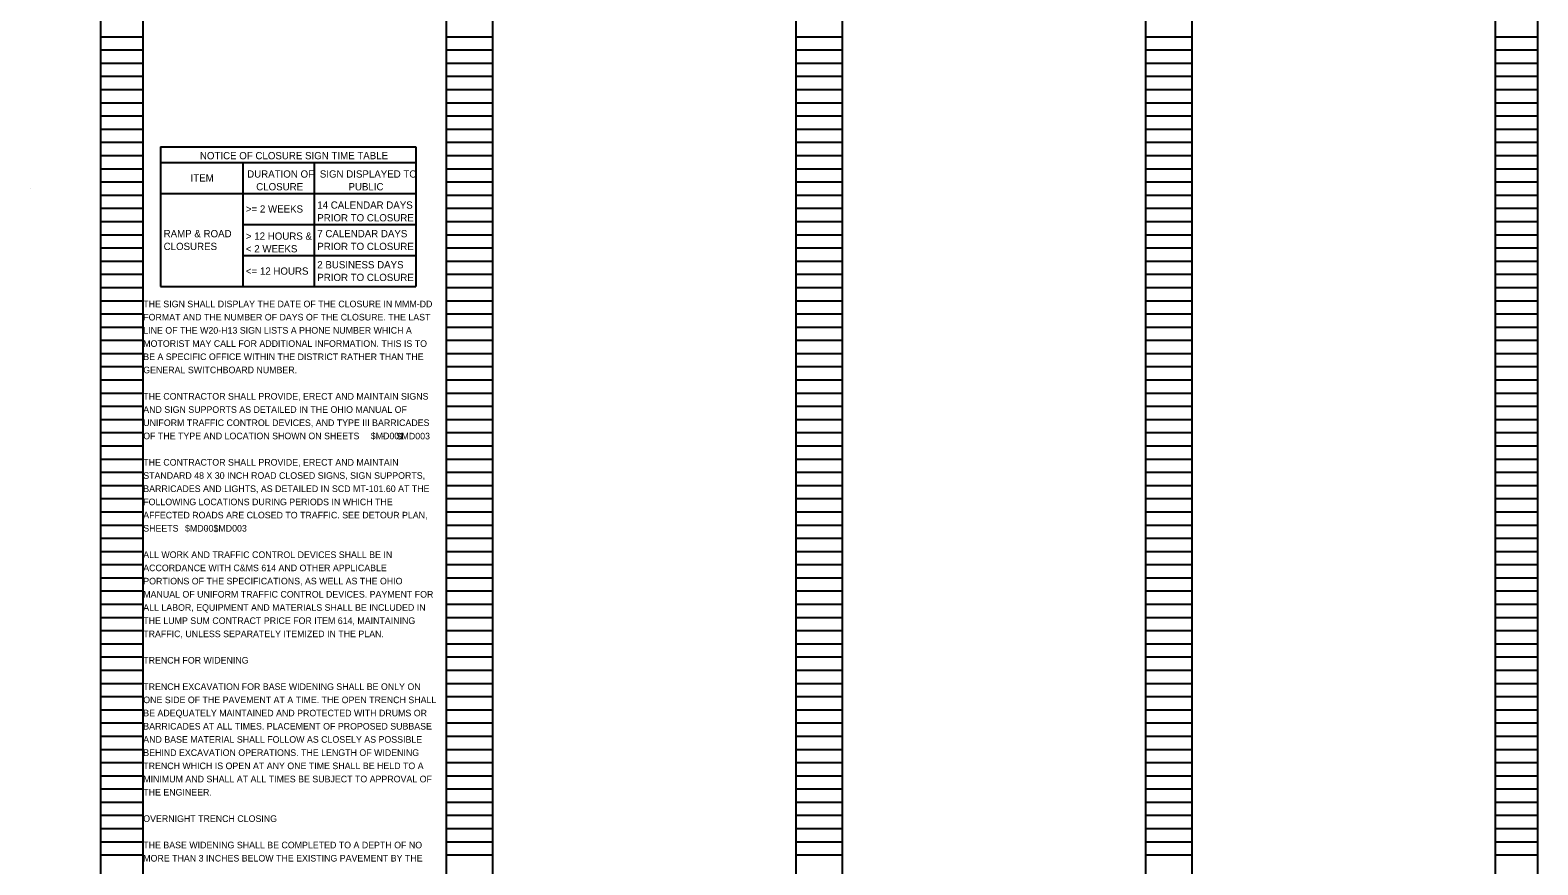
# Model space of a CAD drawing. Extents: x -9 to 32, y -122 to 20.
# Drawn here: x -0.28 to 31.72, y -15.02 to 2.69 of the extents above; entities that cross this region are included whole.
import ezdxf

# ---------------------------------------------------------------- set-up
doc = ezdxf.new("R2010")
doc.units = 0
doc.layers.add('SC_Scratch1', color=7, linetype='Continuous')
doc.layers.add('SH_Text', color=7, linetype='Continuous')

msp = doc.modelspace()

# ---------------------------------------------------------------- linework, layer by layer
at = {"layer": 'SC_Scratch1'}
for p, q in [((1.216, 0.306), (1.216, 20.466)), ((2.116, 0.306), (2.116, 20.466)), ((8.556, 0.306), (8.556, 20.466)), ((9.536, 0.306), (9.536, 20.466)), ((15.976, 0.306), (15.976, 20.466)), ((16.956, 0.306), (16.956, 20.466)), ((23.396, 0.306), (23.396, 20.466)), ((24.376, 0.306), (24.376, 20.466)), ((30.816, 0.306), (30.816, 20.466)), ((31.716, 0.306), (31.716, 20.466)), ((1.216, 2.546), (2.116, 2.546)), ((1.216, 2.266), (2.116, 2.266)), ((8.556, 2.546), (9.536, 2.546)), ((8.556, 2.266), (9.536, 2.266)), ((15.976, 2.546), (16.956, 2.546)), ((15.976, 2.266), (16.956, 2.266)), ((23.396, 2.546), (24.376, 2.546)), ((23.396, 2.266), (24.376, 2.266)), ((30.816, 2.546), (31.716, 2.546)), ((30.816, 2.266), (31.716, 2.266)), ((1.216, 1.986), (2.116, 1.986)), ((8.556, 1.986), (9.536, 1.986)), ((15.976, 1.986), (16.956, 1.986)), ((23.396, 1.986), (24.376, 1.986)), ((30.816, 1.986), (31.716, 1.986)), ((1.216, 1.706), (2.116, 1.706)), ((8.556, 1.706), (9.536, 1.706)), ((15.976, 1.706), (16.956, 1.706)), ((23.396, 1.706), (24.376, 1.706)), ((30.816, 1.706), (31.716, 1.706)), ((1.216, 1.426), (2.116, 1.426)), ((8.556, 1.426), (9.536, 1.426)), ((15.976, 1.426), (16.956, 1.426)), ((23.396, 1.426), (24.376, 1.426)), ((30.816, 1.426), (31.716, 1.426)), ((1.216, 1.146), (2.116, 1.146)), ((8.556, 1.146), (9.536, 1.146)), ((15.976, 1.146), (16.956, 1.146)), ((23.396, 1.146), (24.376, 1.146)), ((30.816, 1.146), (31.716, 1.146)), ((1.216, 0.866), (2.116, 0.866)), ((8.556, 0.866), (9.536, 0.866)), ((15.976, 0.866), (16.956, 0.866)), ((23.396, 0.866), (24.376, 0.866)), ((30.816, 0.866), (31.716, 0.866)), ((1.216, 0.586), (2.116, 0.586)), ((8.556, 0.586), (9.536, 0.586)), ((15.976, 0.586), (16.956, 0.586)), ((23.396, 0.586), (24.376, 0.586)), ((30.816, 0.586), (31.716, 0.586)), ((1.216, 0.306), (2.116, 0.306)), ((1.216, -19.854), (1.216, 0.306)), ((1.216, 0.306), (2.116, 0.306)), ((1.216, 0.026), (2.116, 0.026)), ((2.116, -19.854), (2.116, 0.306)), ((8.556, 0.306), (9.536, 0.306)), ((8.556, -19.854), (8.556, 0.306)), ((8.556, 0.306), (9.536, 0.306)), ((8.556, 0.026), (9.536, 0.026)), ((9.536, -19.854), (9.536, 0.306)), ((15.976, 0.306), (16.956, 0.306)), ((15.976, -19.854), (15.976, 0.306)), ((15.976, 0.306), (16.956, 0.306)), ((15.976, 0.026), (16.956, 0.026)), ((16.956, -19.854), (16.956, 0.306)), ((23.396, 0.306), (24.376, 0.306)), ((23.396, -19.854), (23.396, 0.306)), ((23.396, 0.306), (24.376, 0.306)), ((23.396, 0.026), (24.376, 0.026)), ((24.376, -19.854), (24.376, 0.306)), ((30.816, 0.306), (31.716, 0.306)), ((30.816, -19.854), (30.816, 0.306)), ((30.816, 0.306), (31.716, 0.306)), ((30.816, 0.026), (31.716, 0.026)), ((31.716, -19.854), (31.716, 0.306)), ((1.216, -0.254), (2.116, -0.254)), ((8.556, -0.254), (9.536, -0.254)), ((15.976, -0.254), (16.956, -0.254)), ((23.396, -0.254), (24.376, -0.254)), ((30.816, -0.254), (31.716, -0.254)), ((1.216, -0.534), (2.116, -0.534)), ((8.556, -0.534), (9.536, -0.534)), ((15.976, -0.534), (16.956, -0.534)), ((23.396, -0.534), (24.376, -0.534)), ((30.816, -0.534), (31.716, -0.534)), ((-0.284, -0.674), (-0.284, -0.674)), ((1.216, -0.814), (2.116, -0.814)), ((8.556, -0.814), (9.536, -0.814)), ((15.976, -0.814), (16.956, -0.814)), ((23.396, -0.814), (24.376, -0.814)), ((30.816, -0.814), (31.716, -0.814)), ((1.216, -1.094), (2.116, -1.094)), ((8.556, -1.094), (9.536, -1.094)), ((15.976, -1.094), (16.956, -1.094)), ((23.396, -1.094), (24.376, -1.094)), ((30.816, -1.094), (31.716, -1.094)), ((1.216, -1.374), (2.116, -1.374)), ((8.556, -1.374), (9.536, -1.374)), ((15.976, -1.374), (16.956, -1.374)), ((23.396, -1.374), (24.376, -1.374)), ((30.816, -1.374), (31.716, -1.374)), ((1.216, -1.654), (2.116, -1.654)), ((8.556, -1.654), (9.536, -1.654)), ((15.976, -1.654), (16.956, -1.654)), ((23.396, -1.654), (24.376, -1.654)), ((30.816, -1.654), (31.716, -1.654)), ((1.216, -1.934), (2.116, -1.934)), ((1.216, -2.214), (2.116, -2.214)), ((8.556, -1.934), (9.536, -1.934)), ((8.556, -2.214), (9.536, -2.214)), ((15.976, -1.934), (16.956, -1.934)), ((15.976, -2.214), (16.956, -2.214)), ((23.396, -1.934), (24.376, -1.934)), ((23.396, -2.214), (24.376, -2.214)), ((30.816, -1.934), (31.716, -1.934)), ((30.816, -2.214), (31.716, -2.214)), ((1.216, -2.494), (2.116, -2.494)), ((8.556, -2.494), (9.536, -2.494)), ((15.976, -2.494), (16.956, -2.494)), ((23.396, -2.494), (24.376, -2.494)), ((30.816, -2.494), (31.716, -2.494)), ((1.216, -2.774), (2.116, -2.774)), ((8.556, -2.774), (9.536, -2.774)), ((15.976, -2.774), (16.956, -2.774)), ((23.396, -2.774), (24.376, -2.774)), ((30.816, -2.774), (31.716, -2.774)), ((1.216, -3.054), (2.116, -3.054)), ((8.556, -3.054), (9.536, -3.054)), ((15.976, -3.054), (16.956, -3.054)), ((23.396, -3.054), (24.376, -3.054)), ((30.816, -3.054), (31.716, -3.054)), ((1.216, -3.334), (2.116, -3.334)), ((8.556, -3.334), (9.536, -3.334)), ((15.976, -3.334), (16.956, -3.334)), ((23.396, -3.334), (24.376, -3.334)), ((30.816, -3.334), (31.716, -3.334)), ((1.216, -3.614), (2.116, -3.614)), ((8.556, -3.614), (9.536, -3.614)), ((15.976, -3.614), (16.956, -3.614)), ((23.396, -3.614), (24.376, -3.614)), ((30.816, -3.614), (31.716, -3.614)), ((1.216, -3.894), (2.116, -3.894)), ((8.556, -3.894), (9.536, -3.894)), ((15.976, -3.894), (16.956, -3.894)), ((23.396, -3.894), (24.376, -3.894)), ((30.816, -3.894), (31.716, -3.894)), ((1.216, -4.174), (2.116, -4.174)), ((1.216, -4.454), (2.116, -4.454)), ((8.556, -4.174), (9.536, -4.174)), ((8.556, -4.454), (9.536, -4.454)), ((15.976, -4.174), (16.956, -4.174)), ((15.976, -4.454), (16.956, -4.454)), ((23.396, -4.174), (24.376, -4.174)), ((23.396, -4.454), (24.376, -4.454)), ((30.816, -4.174), (31.716, -4.174)), ((30.816, -4.454), (31.716, -4.454)), ((1.216, -4.734), (2.116, -4.734)), ((8.556, -4.734), (9.536, -4.734)), ((15.976, -4.734), (16.956, -4.734)), ((23.396, -4.734), (24.376, -4.734)), ((30.816, -4.734), (31.716, -4.734)), ((1.216, -5.014), (2.116, -5.014)), ((8.556, -5.014), (9.536, -5.014)), ((15.976, -5.014), (16.956, -5.014)), ((23.396, -5.014), (24.376, -5.014)), ((30.816, -5.014), (31.716, -5.014)), ((1.216, -5.294), (2.116, -5.294)), ((8.556, -5.294), (9.536, -5.294)), ((15.976, -5.294), (16.956, -5.294)), ((23.396, -5.294), (24.376, -5.294)), ((30.816, -5.294), (31.716, -5.294)), ((1.216, -5.574), (2.116, -5.574)), ((8.556, -5.574), (9.536, -5.574)), ((15.976, -5.574), (16.956, -5.574)), ((23.396, -5.574), (24.376, -5.574)), ((30.816, -5.574), (31.716, -5.574)), ((1.216, -5.854), (2.116, -5.854)), ((8.556, -5.854), (9.536, -5.854)), ((15.976, -5.854), (16.956, -5.854)), ((23.396, -5.854), (24.376, -5.854)), ((30.816, -5.854), (31.716, -5.854)), ((1.216, -6.134), (2.116, -6.134)), ((8.556, -6.134), (9.536, -6.134)), ((15.976, -6.134), (16.956, -6.134)), ((23.396, -6.134), (24.376, -6.134)), ((30.816, -6.134), (31.716, -6.134)), ((1.216, -6.414), (2.116, -6.414)), ((1.216, -6.694), (2.116, -6.694)), ((8.556, -6.414), (9.536, -6.414)), ((8.556, -6.694), (9.536, -6.694)), ((15.976, -6.414), (16.956, -6.414)), ((15.976, -6.694), (16.956, -6.694)), ((23.396, -6.414), (24.376, -6.414)), ((23.396, -6.694), (24.376, -6.694)), ((30.816, -6.414), (31.716, -6.414)), ((30.816, -6.694), (31.716, -6.694)), ((1.216, -6.974), (2.116, -6.974)), ((8.556, -6.974), (9.536, -6.974)), ((15.976, -6.974), (16.956, -6.974)), ((23.396, -6.974), (24.376, -6.974)), ((30.816, -6.974), (31.716, -6.974)), ((1.216, -7.254), (2.116, -7.254)), ((8.556, -7.254), (9.536, -7.254)), ((15.976, -7.254), (16.956, -7.254)), ((23.396, -7.254), (24.376, -7.254)), ((30.816, -7.254), (31.716, -7.254)), ((1.216, -7.534), (2.116, -7.534)), ((8.556, -7.534), (9.536, -7.534)), ((15.976, -7.534), (16.956, -7.534)), ((23.396, -7.534), (24.376, -7.534)), ((30.816, -7.534), (31.716, -7.534)), ((1.216, -7.814), (2.116, -7.814)), ((8.556, -7.814), (9.536, -7.814)), ((15.976, -7.814), (16.956, -7.814)), ((23.396, -7.814), (24.376, -7.814)), ((30.816, -7.814), (31.716, -7.814)), ((1.216, -8.094), (2.116, -8.094)), ((8.556, -8.094), (9.536, -8.094)), ((15.976, -8.094), (16.956, -8.094)), ((23.396, -8.094), (24.376, -8.094)), ((30.816, -8.094), (31.716, -8.094)), ((1.216, -8.374), (2.116, -8.374)), ((8.556, -8.374), (9.536, -8.374)), ((15.976, -8.374), (16.956, -8.374)), ((23.396, -8.374), (24.376, -8.374)), ((30.816, -8.374), (31.716, -8.374)), ((1.216, -8.654), (2.116, -8.654)), ((1.216, -8.934), (2.116, -8.934)), ((8.556, -8.654), (9.536, -8.654)), ((8.556, -8.934), (9.536, -8.934)), ((15.976, -8.654), (16.956, -8.654)), ((15.976, -8.934), (16.956, -8.934)), ((23.396, -8.654), (24.376, -8.654)), ((23.396, -8.934), (24.376, -8.934)), ((30.816, -8.654), (31.716, -8.654)), ((30.816, -8.934), (31.716, -8.934)), ((1.216, -9.214), (2.116, -9.214)), ((8.556, -9.214), (9.536, -9.214)), ((15.976, -9.214), (16.956, -9.214)), ((23.396, -9.214), (24.376, -9.214)), ((30.816, -9.214), (31.716, -9.214)), ((1.216, -9.494), (2.116, -9.494)), ((8.556, -9.494), (9.536, -9.494)), ((15.976, -9.494), (16.956, -9.494)), ((23.396, -9.494), (24.376, -9.494)), ((30.816, -9.494), (31.716, -9.494)), ((1.216, -9.774), (2.116, -9.774)), ((8.556, -9.774), (9.536, -9.774)), ((15.976, -9.774), (16.956, -9.774)), ((23.396, -9.774), (24.376, -9.774)), ((30.816, -9.774), (31.716, -9.774)), ((1.216, -10.054), (2.116, -10.054)), ((8.556, -10.054), (9.536, -10.054)), ((15.976, -10.054), (16.956, -10.054)), ((23.396, -10.054), (24.376, -10.054)), ((30.816, -10.054), (31.716, -10.054)), ((1.216, -10.334), (2.116, -10.334)), ((8.556, -10.334), (9.536, -10.334)), ((15.976, -10.334), (16.956, -10.334)), ((23.396, -10.334), (24.376, -10.334)), ((30.816, -10.334), (31.716, -10.334)), ((1.216, -10.614), (2.116, -10.614)), ((8.556, -10.614), (9.536, -10.614)), ((15.976, -10.614), (16.956, -10.614)), ((23.396, -10.614), (24.376, -10.614)), ((30.816, -10.614), (31.716, -10.614)), ((1.216, -10.894), (2.116, -10.894)), ((1.216, -11.174), (2.116, -11.174)), ((8.556, -10.894), (9.536, -10.894)), ((8.556, -11.174), (9.536, -11.174)), ((15.976, -10.894), (16.956, -10.894)), ((15.976, -11.174), (16.956, -11.174)), ((23.396, -10.894), (24.376, -10.894)), ((23.396, -11.174), (24.376, -11.174)), ((30.816, -10.894), (31.716, -10.894)), ((30.816, -11.174), (31.716, -11.174)), ((1.216, -11.454), (2.116, -11.454)), ((8.556, -11.454), (9.536, -11.454)), ((15.976, -11.454), (16.956, -11.454)), ((23.396, -11.454), (24.376, -11.454)), ((30.816, -11.454), (31.716, -11.454)), ((1.216, -11.734), (2.116, -11.734)), ((8.556, -11.734), (9.536, -11.734)), ((15.976, -11.734), (16.956, -11.734)), ((23.396, -11.734), (24.376, -11.734)), ((30.816, -11.734), (31.716, -11.734)), ((1.216, -12.014), (2.116, -12.014)), ((8.556, -12.014), (9.536, -12.014)), ((15.976, -12.014), (16.956, -12.014)), ((23.396, -12.014), (24.376, -12.014)), ((30.816, -12.014), (31.716, -12.014)), ((1.216, -12.294), (2.116, -12.294)), ((8.556, -12.294), (9.536, -12.294)), ((15.976, -12.294), (16.956, -12.294)), ((23.396, -12.294), (24.376, -12.294)), ((30.816, -12.294), (31.716, -12.294)), ((1.216, -12.574), (2.116, -12.574)), ((8.556, -12.574), (9.536, -12.574)), ((15.976, -12.574), (16.956, -12.574)), ((23.396, -12.574), (24.376, -12.574)), ((30.816, -12.574), (31.716, -12.574)), ((1.216, -12.854), (2.116, -12.854)), ((8.556, -12.854), (9.536, -12.854)), ((15.976, -12.854), (16.956, -12.854)), ((23.396, -12.854), (24.376, -12.854)), ((30.816, -12.854), (31.716, -12.854)), ((1.216, -13.134), (2.116, -13.134)), ((1.216, -13.414), (2.116, -13.414)), ((8.556, -13.134), (9.536, -13.134)), ((8.556, -13.414), (9.536, -13.414)), ((15.976, -13.134), (16.956, -13.134)), ((15.976, -13.414), (16.956, -13.414)), ((23.396, -13.134), (24.376, -13.134)), ((23.396, -13.414), (24.376, -13.414)), ((30.816, -13.134), (31.716, -13.134)), ((30.816, -13.414), (31.716, -13.414)), ((1.216, -13.694), (2.116, -13.694)), ((8.556, -13.694), (9.536, -13.694)), ((15.976, -13.694), (16.956, -13.694)), ((23.396, -13.694), (24.376, -13.694)), ((30.816, -13.694), (31.716, -13.694)), ((1.216, -13.974), (2.116, -13.974)), ((8.556, -13.974), (9.536, -13.974)), ((15.976, -13.974), (16.956, -13.974)), ((23.396, -13.974), (24.376, -13.974)), ((30.816, -13.974), (31.716, -13.974)), ((1.216, -14.254), (2.116, -14.254)), ((8.556, -14.254), (9.536, -14.254)), ((15.976, -14.254), (16.956, -14.254)), ((23.396, -14.254), (24.376, -14.254)), ((30.816, -14.254), (31.716, -14.254)), ((1.216, -14.534), (2.116, -14.534)), ((8.556, -14.534), (9.536, -14.534)), ((15.976, -14.534), (16.956, -14.534)), ((23.396, -14.534), (24.376, -14.534)), ((30.816, -14.534), (31.716, -14.534)), ((1.216, -14.814), (2.116, -14.814)), ((8.556, -14.814), (9.536, -14.814)), ((15.976, -14.814), (16.956, -14.814)), ((23.396, -14.814), (24.376, -14.814)), ((30.816, -14.814), (31.716, -14.814))]:
    msp.add_line(p, q, dxfattribs=at)
at = {"layer": 'SH_Text'}
for p, q in [((2.483, 0.21), (7.902, 0.21)), ((2.483, 0.21), (2.483, -2.755)), ((7.902, 0.21), (7.902, -2.755)), ((2.483, -0.12), (7.902, -0.12)), ((4.229, -0.12), (4.229, -2.755)), ((5.744, -0.12), (5.744, -2.755)), ((2.483, -0.779), (7.902, -0.779)), ((4.229, -1.438), (7.902, -1.438)), ((4.229, -2.096), (7.902, -2.096)), ((2.483, -2.755), (7.902, -2.755))]:
    msp.add_line(p, q, dxfattribs=at)

# ---------------------------------------------------------------- texts
for s, height, p in [('NOTICE OF CLOSURE SIGN TIME TABLE', 0.154, (3.319, -0.054)), ('DURATION OF', 0.154, (4.322, -0.443)), ('SIGN DISPLAYED TO', 0.154, (5.864, -0.443)), ('ITEM', 0.154, (3.121, -0.526)), ('CLOSURE', 0.154, (4.514, -0.713)), ('PUBLIC', 0.154, (6.472, -0.713)), ('14 CALENDAR DAYS', 0.154, (5.81, -1.102)), ('>= 2 WEEKS', 0.154, (4.295, -1.185)), ('PRIOR TO CLOSURE', 0.154, (5.81, -1.372)), ('RAMP & ROAD', 0.154, (2.549, -1.709)), ('7 CALENDAR DAYS', 0.154, (5.81, -1.709)), ('CLOSURES', 0.154, (2.549, -1.979)), ('> 12 HOURS &', 0.154, (4.295, -1.761)), ('< 2 WEEKS', 0.154, (4.295, -2.03)), ('PRIOR TO CLOSURE', 0.154, (5.81, -1.979)), ('2 BUSINESS DAYS', 0.154, (5.81, -2.368)), ('<= 12 HOURS', 0.154, (4.295, -2.503)), ('PRIOR TO CLOSURE', 0.154, (5.81, -2.637)), ('THE SIGN SHALL DISPLAY THE DATE OF THE CLOSURE IN MMM-DD ', 0.14, (2.116, -3.194)), ('FORMAT AND THE NUMBER OF DAYS OF THE CLOSURE. THE LAST ', 0.14, (2.116, -3.474)), ('LINE OF THE W20-H13 SIGN LISTS A PHONE NUMBER WHICH A ', 0.14, (2.116, -3.754)), ('MOTORIST MAY CALL FOR ADDITIONAL INFORMATION. THIS IS TO ', 0.14, (2.116, -4.034)), ('GENERAL SWITCHBOARD NUMBER.', 0.14, (2.116, -4.594)), ('BE A SPECIFIC OFFICE WITHIN THE DISTRICT RATHER THAN THE ', 0.14, (2.116, -4.314)), ('THE CONTRACTOR SHALL PROVIDE, ERECT AND MAINTAIN SIGNS ', 0.14, (2.116, -5.154)), ('AND SIGN SUPPORTS AS DETAILED IN THE OHIO MANUAL OF ', 0.14, (2.116, -5.434)), ('UNIFORM TRAFFIC CONTROL DEVICES, AND TYPE III BARRICADES ', 0.14, (2.116, -5.714)), ('OF THE TYPE AND LOCATION SHOWN ON SHEETS         -', 0.14, (2.116, -5.994)), ('$MD001', 0.14, (6.946, -5.994)), ('$MD003', 0.14, (7.494, -5.998)), ('THE CONTRACTOR SHALL PROVIDE, ERECT AND MAINTAIN ', 0.14, (2.116, -6.554)), ('STANDARD 48 X 30 INCH ROAD CLOSED SIGNS, SIGN SUPPORTS, ', 0.14, (2.116, -6.834)), ('BARRICADES AND LIGHTS, AS DETAILED IN SCD MT-101.60 AT THE ', 0.14, (2.116, -7.114)), ('FOLLOWING LOCATIONS DURING PERIODS IN WHICH THE ', 0.14, (2.116, -7.394)), ('AFFECTED ROADS ARE CLOSED TO TRAFFIC. SEE DETOUR PLAN, ', 0.14, (2.116, -7.674)), ('SHEETS           -', 0.14, (2.116, -7.954)), ('$MD001', 0.14, (3.003, -7.954)), ('$MD003', 0.14, (3.607, -7.954)), ('ALL WORK AND TRAFFIC CONTROL DEVICES SHALL BE IN ', 0.14, (2.116, -8.514)), ('ACCORDANCE WITH C&MS 614 AND OTHER APPLICABLE ', 0.14, (2.116, -8.794)), ('PORTIONS OF THE SPECIFICATIONS, AS WELL AS THE OHIO ', 0.14, (2.116, -9.074)), ('MANUAL OF UNIFORM TRAFFIC CONTROL DEVICES. PAYMENT FOR ', 0.14, (2.116, -9.354)), ('ALL LABOR, EQUIPMENT AND MATERIALS SHALL BE INCLUDED IN ', 0.14, (2.116, -9.634)), ('THE LUMP SUM CONTRACT PRICE FOR ITEM 614, MAINTAINING ', 0.14, (2.116, -9.914)), ('TRAFFIC, UNLESS SEPARATELY ITEMIZED IN THE PLAN.', 0.14, (2.116, -10.194)), ('TRENCH FOR WIDENING', 0.14, (2.116, -10.754)), ('TRENCH EXCAVATION FOR BASE WIDENING SHALL BE ONLY ON ', 0.14, (2.116, -11.314)), ('ONE SIDE OF THE PAVEMENT AT A TIME. THE OPEN TRENCH SHALL ', 0.14, (2.116, -11.594)), ('BE ADEQUATELY MAINTAINED AND PROTECTED WITH DRUMS OR ', 0.14, (2.116, -11.874)), ('BARRICADES AT ALL TIMES. PLACEMENT OF PROPOSED SUBBASE ', 0.14, (2.116, -12.154)), ('AND BASE MATERIAL SHALL FOLLOW AS CLOSELY AS POSSIBLE ', 0.14, (2.116, -12.434)), ('BEHIND EXCAVATION OPERATIONS. THE LENGTH OF WIDENING ', 0.14, (2.116, -12.714)), ('TRENCH WHICH IS OPEN AT ANY ONE TIME SHALL BE HELD TO A ', 0.14, (2.116, -12.994)), ('THE ENGINEER.', 0.14, (2.116, -13.554)), ('MINIMUM AND SHALL AT ALL TIMES BE SUBJECT TO APPROVAL OF ', 0.14, (2.116, -13.274)), ('OVERNIGHT TRENCH CLOSING', 0.14, (2.116, -14.114)), ('THE BASE WIDENING SHALL BE COMPLETED TO A DEPTH OF NO ', 0.14, (2.116, -14.674)), ('MORE THAN 3 INCHES BELOW THE EXISTING PAVEMENT BY THE ', 0.14, (2.116, -14.954))]:
    msp.add_text(s, height=height, dxfattribs=at).set_placement(p)

doc.saveas('drawing.dxf')
